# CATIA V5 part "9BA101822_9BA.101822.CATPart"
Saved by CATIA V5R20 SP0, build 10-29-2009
Part number: 9BA101822_9BA.101822
Revision: ANY
Definition: UNKNOWN
Nomenclature: 9BA101822_9BA.101822
Source: Unknown
Bounding box of the stored display mesh (mm): x -10.833 to 10.833, y 0 to 25.5, z -11 to 11
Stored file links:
  C:\Users\Utente\Desktop\IO LAVORO\3D X SITO CF\CUMSA\3D files BA\BA 101822\9BA101822_9BA.101822.CATPart
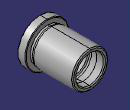
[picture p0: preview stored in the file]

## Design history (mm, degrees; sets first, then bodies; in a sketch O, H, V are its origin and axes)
Body1 "Cortar-Extruir1" (main body)
  Solid1: solid without history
